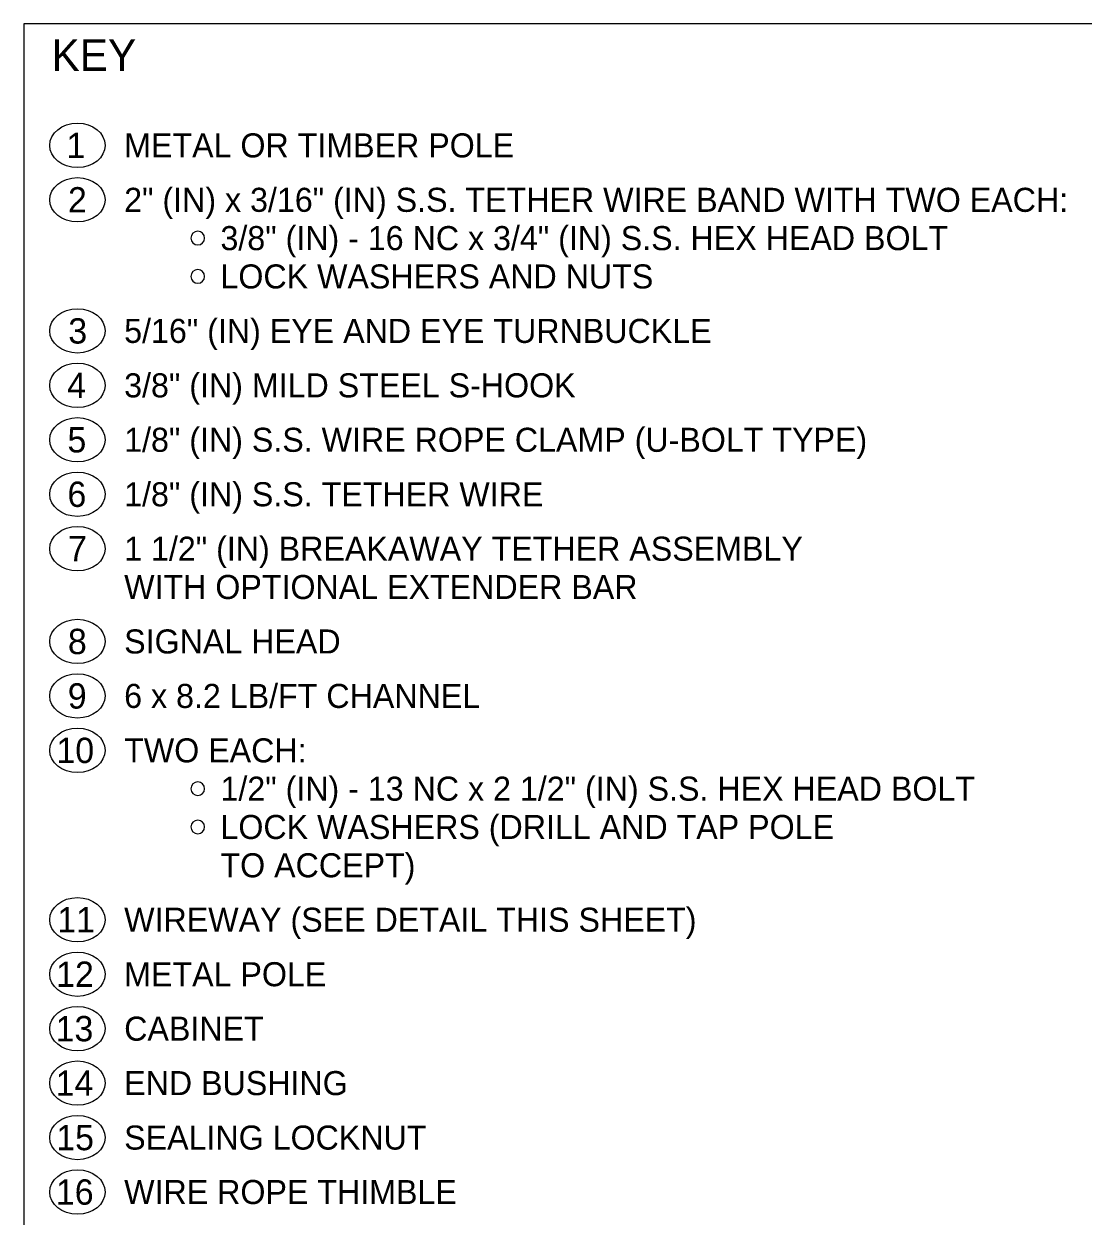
# Model space of a CAD drawing. Extents: x 99862 to 104211, y 98939 to 102076.
# Drawn here: x 99862 to 100531, y 101322 to 102076 of the extents above; entities that cross this region are included whole.
import ezdxf

# ---------------------------------------------------------------- set-up
doc = ezdxf.new("R2010")
doc.units = 0
for name, color, linetype in [('Level 1', 7, 'Continuous'), ('Level 15', 7, 'Continuous'), ('Level 20', 7, 'Continuous')]:
    doc.layers.add(name, color=color, linetype=linetype)

msp = doc.modelspace()

# ---------------------------------------------------------------- linework, layer by layer
at = {"layer": 'Level 1'}
msp.add_lwpolyline([(99862, 99999.5), (103151, 99999.5), (103151, 102075.5), (99862, 102075.5)], close=True, dxfattribs=at)
at = {"layer": 'Level 20'}
for centre, start, end in [((99971.8, 101940.13), 0, 180), ((99971.8, 101940.13), 180, 0), ((99971.8, 101915.93), 0, 180), ((99971.8, 101915.93), 180, 0), ((99971.8, 101592.33), 0, 180), ((99971.8, 101592.33), 180, 0), ((99971.8, 101568.13), 0, 180), ((99971.8, 101568.13), 180, 0)]:
    msp.add_arc(centre, 4.33, start, end, dxfattribs=at)
for centre in [(99895.84, 101998.73), (99895.84, 101964.33), (99895.84, 101881.53), (99895.84, 101847.13), (99895.84, 101812.73), (99895.84, 101778.33), (99895.84, 101743.93), (99895.84, 101685.33), (99895.84, 101650.93), (99895.84, 101616.53), (99895.84, 101509.53), (99895.84, 101475.13), (99895.84, 101440.73), (99895.84, 101406.33), (99895.84, 101371.93), (99895.84, 101337.53)]:
    msp.add_ellipse(centre, major_axis=(-17.5, 0), ratio=0.8, dxfattribs=at)

# ---------------------------------------------------------------- texts
at = {"layer": 'Level 15'}
for s, p in [('METAL OR TIMBER POLE', (99925.34, 101991.13)), ('2" (IN) x 3/16" (IN) S.S. TETHER WIRE BAND WITH TWO EACH:', (99925.34, 101956.73)), ('3/8" (IN) - 16 NC x 3/4" (IN) S.S. HEX HEAD BOLT', (99986.14, 101932.53)), ('LOCK WASHERS AND NUTS', (99986.14, 101908.33)), ('5/16" (IN) EYE AND EYE TURNBUCKLE', (99925.34, 101873.93)), ('3/8" (IN) MILD STEEL S-HOOK', (99925.34, 101839.53)), ('1/8" (IN) S.S. WIRE ROPE CLAMP (U-BOLT TYPE)', (99925.34, 101805.13)), ('1/8" (IN) S.S. TETHER WIRE', (99925.34, 101770.73)), ('1 1/2" (IN) BREAKAWAY TETHER ASSEMBLY', (99925.34, 101736.33)), ('WITH OPTIONAL EXTENDER BAR', (99925.34, 101712.13)), ('SIGNAL HEAD', (99925.34, 101677.73)), ('6 x 8.2 LB/FT CHANNEL', (99925.34, 101643.33)), ('TWO EACH:', (99925.34, 101608.93)), ('1/2" (IN) - 13 NC x 2 1/2" (IN) S.S. HEX HEAD BOLT', (99986.14, 101584.73)), ('LOCK WASHERS (DRILL AND TAP POLE', (99986.14, 101560.53)), ('TO ACCEPT)', (99986.14, 101536.33)), ('WIREWAY (SEE DETAIL THIS SHEET)', (99925.34, 101501.93)), ('METAL POLE', (99925.34, 101467.53)), ('CABINET', (99925.34, 101433.13)), ('END BUSHING', (99925.34, 101398.73)), ('SEALING LOCKNUT', (99925.34, 101364.33)), ('WIRE ROPE THIMBLE', (99925.34, 101329.93))]:
    msp.add_text(s, height=15.2, dxfattribs=at).set_placement(p)
at = {"layer": 'Level 20'}
for s, height, p in [('KEY', 20, (99879.43, 102045.73)), ('1', 16, (99888.97, 101990.73)), ('2', 16, (99889.85, 101956.33)), ('3', 16, (99890.05, 101873.53)), ('4', 16, (99889.33, 101839.13)), ('5', 16, (99889.53, 101804.73)), ('6', 16, (99889.53, 101770.33)), ('7', 16, (99889.89, 101735.93)), ('8', 16, (99889.82, 101677.33)), ('9', 16, (99889.74, 101642.93)), ('10', 16, (99882.58, 101608.53)), ('11', 16, (99883.11, 101501.53)), ('12', 16, (99882.4, 101467.13)), ('13', 16, (99882.06, 101432.73)), ('14', 16, (99882.06, 101398.33)), ('15', 16, (99882.46, 101363.93)), ('16', 16, (99882.24, 101329.53))]:
    msp.add_text(s, height=height, dxfattribs=at).set_placement(p)

doc.saveas('drawing.dxf')
